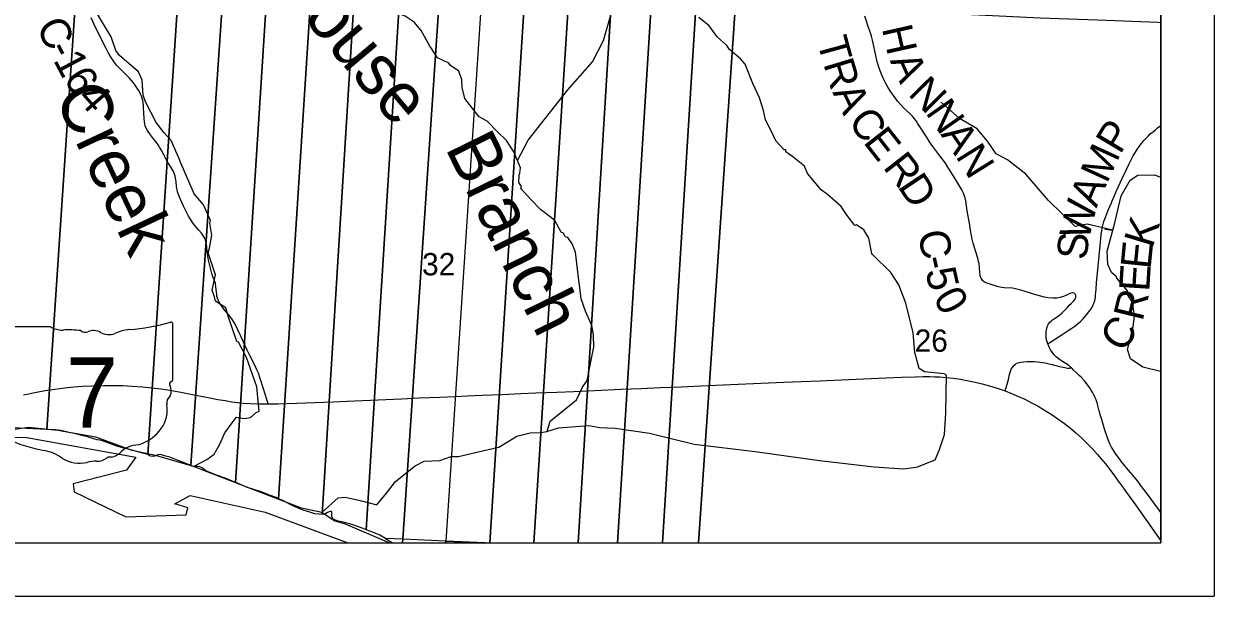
# Model space of a CAD drawing. Extents: x 0 to 34, y 0 to 22.
# Drawn here: x 6.766 to 9, y 14 to 15.074 of the extents above; entities that cross this region are included whole.
import ezdxf

# ---------------------------------------------------------------- set-up
doc = ezdxf.new("R2010")
doc.units = 0
for name, color, linetype in [('Default', 7, 'Continuous'), ('GM_X_County_Road', 7, 'Continuous'), ('GM_X_County_Road_Text', 7, 'Continuous'), ('GM_X_Major_River', 7, 'Continuous'), ('GM_X_Minor_River', 7, 'Continuous'), ('GM_X_Minor_River_Text', 7, 'Continuous'), ('GM_X_Section', 7, 'Continuous'), ('GM_X_Section_Text', 7, 'Continuous'), ('GM_X_State_Route', 7, 'Continuous'), ('GM_X_State_Shield', 7, 'Continuous'), ('SH_Cut_Line', 7, 'Continuous'), ('SH_Data', 7, 'Continuous')]:
    doc.layers.add(name, color=color, linetype=linetype)

msp = doc.modelspace()

# ---------------------------------------------------------------- linework, layer by layer
at = {"layer": 'Default'}
msp.add_lwpolyline([(6.746, 14.2985), (6.7712, 14.2974), (6.976, 14.2607), (6.9586, 14.2364), (6.8584, 14.2105), (6.8604, 14.196), (6.9571, 14.149), (7.0704, 14.1528), (7.0738, 14.1658), (7.0492, 14.1735), (7.0778, 14.1886), (7.2187, 14.1579), (7.3738, 14.1), (8.9, 14.1), (8.9, 19.1797)], dxfattribs=at)
for points in [[(7.6316, 14.1), (7.6406, 14.1), (7.7063, 15.1284), (7.6256, 15.132), (7.558, 14.1033)], [(7.6406, 14.1), (7.7231, 14.1), (7.7887, 15.1248), (7.7089, 15.1283), (7.7063, 15.1284)], [(7.7231, 14.1), (7.806, 14.1), (7.8688, 15.1212), (7.7887, 15.1248)], [(7.806, 14.1), (7.88, 14.1), (7.9439, 15.1179), (7.8688, 15.1212)], [(7.88, 14.1), (7.9647, 14.1), (8.0279, 15.1141), (7.9439, 15.1179)], [(7.9647, 14.1), (8.0319, 14.1), (8.1017, 15.1109), (8.0279, 15.1141)], [(8.0319, 14.1), (8.9, 14.1), (8.9, 15.0758), (8.8945, 15.0761), (8.7811, 15.0807), (8.6731, 15.0846), (8.5585, 15.09), (8.4462, 15.0952), (8.3272, 15.1001), (8.2115, 15.1046), (8.1017, 15.1109)], [(7.4602, 14.1), (7.4765, 14.1), (7.477, 14.1069), (7.4448, 14.1083), (7.453, 14.103), (7.4572, 14.1007)], [(7.4765, 14.1), (7.5578, 14.1), (7.558, 14.1033), (7.477, 14.1069)], [(7.5578, 14.1), (7.6316, 14.1), (7.558, 14.1033)]]:
    msp.add_lwpolyline(points, close=True, dxfattribs=at)
at = {"layer": 'GM_X_County_Road'}
for points in [[(7.2244, 14.3606), (7.2219, 14.3688), (7.2156, 14.3892), (7.2096, 14.4082), (7.206, 14.4183), (7.2034, 14.4246), (7.2015, 14.4291), (7.1959, 14.4397), (7.1898, 14.4516), (7.1852, 14.4614), (7.178, 14.4767), (7.173, 14.4881), (7.1675, 14.4999), (7.1622, 14.5106), (7.1573, 14.5185), (7.1524, 14.5252), (7.1418, 14.538), (7.1353, 14.5466), (7.1322, 14.5513), (7.1303, 14.5553), (7.129, 14.5592), (7.1282, 14.5625), (7.1277, 14.5666), (7.1273, 14.5709), (7.1262, 14.5801), (7.1252, 14.5863), (7.1229, 14.5932), (7.1204, 14.5994), (7.1185, 14.6053), (7.1152, 14.6178), (7.1124, 14.6304), (7.1111, 14.6381), (7.1099, 14.6469), (7.109, 14.6552), (7.1079, 14.6638), (7.107, 14.6679), (7.1051, 14.6721), (7.103, 14.6757), (7.099, 14.6811), (7.0942, 14.6868), (7.0898, 14.6919), (7.0867, 14.6955), (7.0823, 14.7011), (7.0784, 14.707), (7.0751, 14.7129), (7.0657, 14.7315), (7.0584, 14.7471), (7.0559, 14.7538), (7.0543, 14.7586), (7.0538, 14.7622), (7.0526, 14.7686), (7.0516, 14.7771), (7.0512, 14.781), (7.0506, 14.7848), (7.0499, 14.7877), (7.0485, 14.7918), (7.0458, 14.7978), (7.0385, 14.8096), (7.0352, 14.815), (7.0318, 14.8216), (7.0277, 14.8295), (7.0237, 14.8371), (7.0206, 14.8426), (7.0177, 14.8469), (7.0149, 14.851), (7.0092, 14.8583), (7.0033, 14.8654), (6.9976, 14.8735), (6.9955, 14.8779), (6.9937, 14.8823), (6.9929, 14.8862), (6.9923, 14.8895), (6.9914, 14.8967), (6.991, 14.9063), (6.9906, 14.9168), (6.9904, 14.9207), (6.9899, 14.9259), (6.9893, 14.9298), (6.9881, 14.9345), (6.9866, 14.9381), (6.9848, 14.9418), (6.9832, 14.9451), (6.9811, 14.949), (6.9785, 14.9532), (6.9745, 14.9589), (6.9709, 14.9638), (6.9678, 14.9676), (6.9638, 14.9719), (6.9609, 14.975), (6.9557, 14.9799), (6.9519, 14.9836), (6.9469, 14.9884), (6.9398, 14.9964), (6.9347, 15.003), (6.9297, 15.0108), (6.9268, 15.0156), (6.9243, 15.0199), (6.9197, 15.0287), (6.9161, 15.0355), (6.9122, 15.044), (6.9012, 15.0659), (6.8919, 15.0851)], [(8.6876, 14.4735), (8.6863, 14.4774), (8.6853, 14.4808), (8.6848, 14.4851), (8.6846, 14.4894), (8.6847, 14.4944), (8.6853, 14.5008), (8.6864, 14.5046), (8.6873, 14.5074), (8.6893, 14.511), (8.6916, 14.5139), (8.6937, 14.5162), (8.6968, 14.5187), (8.7022, 14.5224), (8.7069, 14.5254), (8.7104, 14.5279), (8.7146, 14.5314), (8.7202, 14.537), (8.7248, 14.5418), (8.7274, 14.5452), (8.7319, 14.5495), (8.7361, 14.5535), (8.7384, 14.5563), (8.7397, 14.5589), (8.7403, 14.5612), (8.7404, 14.5628), (8.7402, 14.5646), (8.7395, 14.5662), (8.7385, 14.5675), (8.7371, 14.5686), (8.7354, 14.5691), (8.7335, 14.5692), (8.7312, 14.5686), (8.7281, 14.5674), (8.723, 14.5648), (8.7169, 14.5624), (8.7103, 14.5602), (8.7044, 14.5594), (8.6979, 14.5588), (8.6879, 14.5599), (8.6818, 14.561), (8.6697, 14.5641), (8.6589, 14.567), (8.6434, 14.5721), (8.6348, 14.5749), (8.6273, 14.5768), (8.6213, 14.5776), (8.606, 14.5785), (8.6017, 14.5788), (8.5977, 14.5796), (8.5927, 14.5811), (8.5776, 14.5858), (8.572, 14.5878), (8.5689, 14.5892), (8.566, 14.5916), (8.5637, 14.5946), (8.5626, 14.5968), (8.5615, 14.5992), (8.5608, 14.6023), (8.5601, 14.6073), (8.5594, 14.6166), (8.5586, 14.6243), (8.5579, 14.6278), (8.5562, 14.6343), (8.552, 14.6477), (8.5477, 14.662), (8.5457, 14.6697), (8.5443, 14.6765), (8.5428, 14.6867), (8.5408, 14.7001), (8.5397, 14.7061), (8.5378, 14.7163), (8.5364, 14.7232), (8.5351, 14.7326), (8.5338, 14.7415), (8.5324, 14.7475), (8.5309, 14.7524), (8.5294, 14.7558), (8.5261, 14.7624), (8.5149, 14.781), (8.5055, 14.7963), (8.5003, 14.8048), (8.4956, 14.8122), (8.4894, 14.8206), (8.4834, 14.8285), (8.4719, 14.8439), (8.4659, 14.8525), (8.4612, 14.8596), (8.4469, 14.882), (8.4432, 14.8876), (8.4405, 14.8916), (8.4376, 14.8958), (8.4336, 14.9005), (8.4292, 14.9047), (8.4175, 14.9158), (8.4123, 14.9211), (8.4065, 14.9278), (8.4009, 14.935), (8.393, 14.9464), (8.3877, 14.9547), (8.3839, 14.9616), (8.3789, 14.9718), (8.3742, 14.9826), (8.3711, 14.9907), (8.3687, 14.9985), (8.3669, 15.0049), (8.3656, 15.011), (8.3632, 15.0228), (8.3613, 15.0316), (8.3588, 15.0431), (8.3567, 15.0506), (8.3553, 15.0548), (8.3519, 15.0653), (8.3441, 15.0884)], [(8.6876, 14.4735), (8.6885, 14.474), (8.6914, 14.4757), (8.7022, 14.4827), (8.7148, 14.4909), (8.7259, 14.4983), (8.733, 14.503), (8.7384, 14.5068), (8.7428, 14.51), (8.7456, 14.5124), (8.7496, 14.5161), (8.7528, 14.5192), (8.7568, 14.5234), (8.7605, 14.5278), (8.7649, 14.5333), (8.7694, 14.5392), (8.7722, 14.5446), (8.7743, 14.5495), (8.7755, 14.5531), (8.7764, 14.557), (8.7772, 14.5616), (8.7775, 14.5653), (8.7782, 14.5752), (8.779, 14.5882), (8.7808, 14.6059), (8.7821, 14.6193), (8.7833, 14.6317), (8.7847, 14.6455), (8.787, 14.6698), (8.788, 14.6789), (8.7888, 14.6853), (8.7895, 14.6893), (8.7904, 14.6932), (8.7931, 14.7027), (8.7964, 14.7125), (8.8011, 14.724), (8.807, 14.7379), (8.8087, 14.7419), (8.8115, 14.7487), (8.8162, 14.759), (8.8272, 14.7836), (8.8345, 14.799), (8.8398, 14.8101), (8.8479, 14.8262), (8.8521, 14.8333), (8.8574, 14.8414), (8.8615, 14.8468), (8.8643, 14.8501), (8.8682, 14.8549), (8.8729, 14.8601), (8.8762, 14.8633), (8.8801, 14.8671), (8.8858, 14.8718), (8.8896, 14.8749), (8.8939, 14.8784), (8.9, 14.8832)], [(8.732, 14.4284), (8.7303, 14.4299), (8.728, 14.4321), (8.7231, 14.4357), (8.7205, 14.4374), (8.7151, 14.4404), (8.7094, 14.4442), (8.7041, 14.4486), (8.6995, 14.4528), (8.6956, 14.4578), (8.6927, 14.4624), (8.6909, 14.4659), (8.6894, 14.4688), (8.6881, 14.472), (8.6876, 14.4735)], [(8.6074, 14.3851), (8.6113, 14.3976), (8.6137, 14.4066), (8.6159, 14.4156), (8.6172, 14.4204), (8.6182, 14.4233), (8.6192, 14.4259), (8.6208, 14.4287), (8.6225, 14.4312), (8.6241, 14.433), (8.6262, 14.4348), (8.6282, 14.4363), (8.6313, 14.4378), (8.6341, 14.4386), (8.6373, 14.4392), (8.6429, 14.4398), (8.6491, 14.4402), (8.6558, 14.4405), (8.6624, 14.4404), (8.6686, 14.4399), (8.6729, 14.4393), (8.6779, 14.4385), (8.683, 14.4375), (8.6877, 14.4365), (8.6959, 14.4344), (8.7098, 14.4311), (8.7194, 14.4288), (8.7248, 14.4279), (8.7287, 14.4278), (8.732, 14.4284)], [(8.9, 14.1572), (8.8974, 14.1607), (8.8868, 14.1749), (8.8767, 14.1886), (8.8681, 14.2002), (8.8624, 14.2079), (8.8564, 14.2156), (8.8496, 14.2236), (8.8287, 14.2492), (8.8223, 14.2576), (8.816, 14.266), (8.8133, 14.2698), (8.8096, 14.2755), (8.8074, 14.2795), (8.8041, 14.2861), (8.8011, 14.2933), (8.7983, 14.3009), (8.7947, 14.3116), (8.792, 14.3199), (8.7888, 14.3314), (8.7869, 14.3382), (8.7843, 14.3479), (8.7822, 14.3554), (8.7801, 14.3626), (8.7782, 14.3682), (8.7764, 14.3724), (8.7745, 14.3767), (8.7722, 14.3813), (8.7691, 14.3868), (8.7663, 14.391), (8.7624, 14.3966), (8.7569, 14.4035), (8.7502, 14.4109), (8.7467, 14.4143), (8.7435, 14.4173), (8.7412, 14.4194), (8.7356, 14.4247), (8.7341, 14.4263), (8.7333, 14.4271), (8.732, 14.4284)]]:
    msp.add_lwpolyline(points, dxfattribs=at)
at = {"layer": 'GM_X_Major_River'}
msp.add_lwpolyline([(7.4517, 14.1), (7.3694, 14.135), (7.3482, 14.1414), (7.3254, 14.1569), (7.2868, 14.1652), (7.1927, 14.2015), (7.0843, 14.2435), (7.0153, 14.2635), (6.969, 14.2733), (6.9012, 14.2986), (6.8397, 14.3092), (6.8303, 14.3107), (6.7738, 14.3167), (6.7492, 14.3128)], dxfattribs=at)
at = {"layer": 'GM_X_Minor_River'}
for points in [[(7.6922, 14.8173), (7.7125, 14.8558), (7.7868, 14.9502), (7.8334, 15.0027), (7.8539, 15.0426), (7.8692, 15.0968), (7.8662, 15.1356), (7.8471, 15.1674), (7.8077, 15.2028), (7.7982, 15.2263), (7.7898, 15.2607), (7.7756, 15.2893), (7.7455, 15.3305), (7.7326, 15.354), (7.7183, 15.4065)], [(7.5633, 15.0001), (7.5423, 15.0098), (7.5298, 15.0295), (7.5279, 15.0318), (7.5116, 15.0614), (7.4987, 15.0766), (7.4817, 15.0883), (7.4636, 15.0947), (7.439, 15.1095), (7.4333, 15.1099), (7.4318, 15.1159), (7.4216, 15.1205), (7.4095, 15.1349), (7.3898, 15.1459), (7.3845, 15.1508), (7.3739, 15.158), (7.3535, 15.199), (7.3213, 15.2502), (7.3201, 15.2582), (7.302, 15.3), (7.3016, 15.3106), (7.3, 15.3167), (7.2982, 15.3155)], [(7.0843, 14.2435), (7.109, 14.2563), (7.1233, 14.2662), (7.1331, 14.2841), (7.1433, 14.3066), (7.1603, 14.3302), (7.1652, 14.3359), (7.18, 14.3332), (7.1913, 14.3352), (7.2019, 14.3443), (7.2072, 14.3474), (7.2033, 14.3926), (7.1836, 14.448), (7.1689, 14.4765), (7.1658, 14.4776), (7.1511, 14.5198), (7.1499, 14.5236), (7.1446, 14.5407), (7.1253, 14.5532), (7.1234, 14.5615), (7.1193, 14.5744), (7.1257, 14.603), (7.112, 14.644), (7.1143, 14.6527), (7.1188, 14.6774), (7.115, 14.6998), (7.1161, 14.7048), (7.1029, 14.734), (7.0855, 14.7549), (7.0589, 14.8152), (7.0582, 14.8194), (7.0423, 14.8547), (7.029, 14.8695), (7.0139, 14.8885), (6.9942, 14.9272), (6.99, 14.9397), (6.9881, 14.9682), (6.9809, 14.9834), (6.9454, 15.0141), (6.9385, 15.0236), (6.9298, 15.0491), (6.917, 15.0699), (6.9014, 15.0965)], [(7.7475, 14.3087), (7.7693, 14.316), (7.7939, 14.3175), (7.8264, 14.3203), (7.8468, 14.3165), (7.8755, 14.3154), (7.9398, 14.3057), (8.0241, 14.2854), (8.1383, 14.2712), (8.2593, 14.2547), (8.3618, 14.2424), (8.4166, 14.2391), (8.4404, 14.2419), (8.4434, 14.2426), (8.4763, 14.256), (8.4846, 14.275), (8.494, 14.3035), (8.4966, 14.3442), (8.4977, 14.4145), (8.4931, 14.4172), (8.4565, 14.4209), (8.4463, 14.4273), (8.4383, 14.4573), (8.4352, 14.4942), (8.4212, 14.55), (8.4083, 14.5842), (8.3928, 14.6074), (8.3584, 14.6407), (8.3572, 14.6426), (8.3519, 14.6715), (8.3421, 14.687), (8.3288, 14.6965), (8.3258, 14.6957), (8.3111, 14.714), (8.2997, 14.731), (8.2743, 14.7534), (8.2626, 14.7625), (8.2369, 14.7932), (8.2312, 14.8069), (8.2093, 14.8243), (8.196, 14.8334), (8.196, 14.8372), (8.1926, 14.8372), (8.1775, 14.8543), (8.1722, 14.8649), (8.1703, 14.8695), (8.1578, 14.8934), (8.154, 14.9112), (8.1468, 14.9348), (8.1339, 14.9621), (8.1195, 14.9982), (8.1112, 15.0084), (8.09, 15.0255), (8.0851, 15.0334), (8.0673, 15.0494), (8.0522, 15.0698), (8.0325, 15.0854)], [(7.3254, 14.1569), (7.3555, 14.1843), (7.3691, 14.1858), (7.3997, 14.1791), (7.4281, 14.1715), (7.4466, 14.1932), (7.4636, 14.2149), (7.5002, 14.2447), (7.5172, 14.2531), (7.5467, 14.2547), (7.5679, 14.2623), (7.5815, 14.2623), (7.6374, 14.275), (7.6575, 14.2796), (7.6858, 14.2972), (7.6911, 14.3002), (7.7164, 14.3063), (7.7357, 14.3071), (7.7478, 14.3087), (7.7534, 14.3281), (7.7606, 14.3338), (7.8029, 14.3685), (7.8146, 14.3921), (7.8233, 14.4046), (7.8301, 14.4396), (7.8357, 14.4674), (7.8353, 14.4902), (7.8319, 14.5076), (7.8198, 14.535), (7.8118, 14.5578), (7.808, 14.5889), (7.8076, 14.5923), (7.8015, 14.6455), (7.7951, 14.6611), (7.7868, 14.6729), (7.7819, 14.674), (7.7788, 14.6808), (7.7743, 14.6831), (7.7622, 14.7047), (7.7535, 14.7119), (7.7353, 14.7256), (7.7175, 14.7445), (7.6986, 14.765), (7.6997, 14.7684), (7.6948, 14.776), (7.6956, 14.7905), (7.6967, 14.7939), (7.6978, 14.8034), (7.6853, 14.8338), (7.6717, 14.855), (7.6547, 14.8713), (7.6354, 14.891), (7.6202, 14.8994), (7.6127, 14.9089), (7.5934, 14.9335), (7.5888, 14.9544), (7.588, 14.9685), (7.582, 14.9848), (7.5668, 14.9958), (7.5632, 15.0002)], [(8.7949, 14.6887), (8.8097, 14.6865), (8.7616, 14.6977), (8.7388, 14.6935), (8.6889, 14.7425), (8.6465, 14.7917), (8.6118, 14.8183), (8.5909, 14.8296), (8.5747, 14.8536), (8.555, 14.8767), (8.5219, 14.8963), (8.4877, 14.9271)], [(8.9, 14.4213), (8.8995, 14.4215), (8.8659, 14.4298), (8.8432, 14.445), (8.8375, 14.4628), (8.848, 14.5046), (8.8503, 14.5263), (8.8469, 14.5518), (8.8381, 14.565), (8.837, 14.573), (8.8173, 14.5969), (8.8166, 14.5992), (8.8075, 14.6075), (8.8003, 14.6223), (8.7991, 14.647), (8.8135, 14.7007), (8.8251, 14.7509), (8.8425, 14.7802), (8.8569, 14.7901), (8.8871, 14.7905), (8.9, 14.7863)]]:
    msp.add_lwpolyline(points, dxfattribs=at)
at = {"layer": 'GM_X_Section'}
for points in [[(6.6679, 15.168), (6.8659, 15.1648), (6.8091, 14.313), (6.7968, 14.3133), (6.7574, 14.3154), (6.7525, 14.3161), (6.7499, 14.3155), (6.742, 14.3162), (6.7242, 14.3154), (6.7094, 14.3154), (6.7014, 14.3158), (6.6848, 14.315), (6.6749, 14.3142), (6.656, 14.3134), (6.6393, 14.313), (6.6211, 14.3149), (6.6082, 14.3162)], [(6.8659, 15.1648), (7.0576, 15.1572), (6.9982, 14.2655), (6.9883, 14.2685), (6.9712, 14.273), (6.9538, 14.2778), (6.9424, 14.2808), (6.9219, 14.2883), (6.9136, 14.2913), (6.9083, 14.2928), (6.9034, 14.2932), (6.8992, 14.2947), (6.8855, 14.2988), (6.8722, 14.3022), (6.8635, 14.3044), (6.851, 14.307), (6.8351, 14.3107), (6.8249, 14.3118), (6.8091, 14.313)], [(7.1412, 15.1536), (7.0789, 14.2451), (7.0683, 14.2494), (7.0524, 14.2558), (7.0459, 14.2584), (7.0399, 14.2607), (7.03, 14.2633), (7.022, 14.2656), (7.0175, 14.2652), (7.0126, 14.2633), (7.0088, 14.2621), (7.0042, 14.2625), (7.0016, 14.2632), (6.9982, 14.2655), (7.0576, 15.1572)], [(7.2228, 15.15), (7.1628, 14.2135), (7.1438, 14.2213), (7.1275, 14.2273), (7.1104, 14.2337), (7.1051, 14.237), (7.1006, 14.2408), (7.0964, 14.2427), (7.0918, 14.2431), (7.0854, 14.2434), (7.0812, 14.2442), (7.0789, 14.2451), (7.1412, 15.1536)], [(7.3055, 15.1463), (7.2438, 14.1829), (7.2394, 14.1849), (7.2288, 14.189), (7.2102, 14.1961), (7.2011, 14.1991), (7.184, 14.2047), (7.1666, 14.2119), (7.1628, 14.2135), (7.2228, 15.15)], [(7.3872, 15.1426), (7.3259, 14.1534), (7.3203, 14.1537), (7.3119, 14.1548), (7.3024, 14.1574), (7.2903, 14.1615), (7.2751, 14.1675), (7.2679, 14.1709), (7.252, 14.1792), (7.2438, 14.1829), (7.3055, 15.1463)], [(7.472, 15.1389), (7.4083, 14.1246), (7.4029, 14.1267), (7.3851, 14.1331), (7.3771, 14.1357), (7.3692, 14.1376), (7.3635, 14.1394), (7.3559, 14.1406), (7.351, 14.1424), (7.3468, 14.1447), (7.3449, 14.1466), (7.3441, 14.1492), (7.3441, 14.156), (7.3437, 14.1579), (7.343, 14.1587), (7.3418, 14.1591), (7.3407, 14.1591), (7.3358, 14.1568), (7.3305, 14.1541), (7.3259, 14.1534), (7.3872, 15.1426)], [(7.5463, 15.1356), (7.477, 14.1069), (7.4448, 14.1083), (7.4337, 14.1143), (7.4219, 14.1192), (7.4083, 14.1246), (7.472, 15.1389)], [(7.6256, 15.132), (7.558, 14.1033), (7.477, 14.1069), (7.5463, 15.1356)]]:
    msp.add_lwpolyline(points, close=True, dxfattribs=at)
at = {"layer": 'GM_X_State_Route'}
msp.add_lwpolyline([(6.7652, 14.3776), (6.7896, 14.3827), (6.806, 14.3857), (6.8239, 14.3884), (6.843, 14.3909), (6.8594, 14.3926), (6.8759, 14.3939), (6.8933, 14.3948), (6.9157, 14.3953), (6.9325, 14.3954), (6.9517, 14.395), (6.9691, 14.3941), (6.9886, 14.3927), (7.0058, 14.391), (7.0227, 14.389), (7.0401, 14.3862), (7.0574, 14.3831), (7.0889, 14.3769), (7.115, 14.3718), (7.1299, 14.3691), (7.1437, 14.3668), (7.1559, 14.3649), (7.167, 14.3634), (7.1775, 14.3623), (7.191, 14.3614), (7.2065, 14.3608), (7.2244, 14.3606), (7.2425, 14.3609), (7.2779, 14.3621), (7.3456, 14.3649), (7.3872, 14.3667), (7.4747, 14.3705), (7.5076, 14.372), (7.5467, 14.3736), (7.5746, 14.3747), (7.5988, 14.3757), (7.6262, 14.3769), (7.6635, 14.3785), (7.6989, 14.3801), (7.7266, 14.3812), (7.7659, 14.3828), (7.7982, 14.3843), (7.8376, 14.386), (7.8868, 14.3881), (7.9245, 14.3898), (7.9606, 14.3914), (7.9997, 14.393), (8.0363, 14.3946), (8.1064, 14.3977), (8.1921, 14.4014), (8.2247, 14.4027), (8.2604, 14.4042), (8.3138, 14.4066), (8.3845, 14.4096), (8.4131, 14.4109), (8.4387, 14.4117), (8.4535, 14.412), (8.4663, 14.412), (8.4754, 14.4118), (8.4844, 14.4113), (8.4973, 14.4103), (8.5101, 14.4089), (8.5238, 14.407), (8.5359, 14.4048), (8.5511, 14.4017), (8.5645, 14.3985), (8.5783, 14.3947), (8.5925, 14.3903), (8.6074, 14.3851), (8.6195, 14.3805), (8.6327, 14.3749), (8.6445, 14.3694), (8.6573, 14.363), (8.6693, 14.3564), (8.6817, 14.3492), (8.6943, 14.3412), (8.7067, 14.3328), (8.7193, 14.3237), (8.7301, 14.3152), (8.7406, 14.3064), (8.7512, 14.2968), (8.7606, 14.2877), (8.7709, 14.2769), (8.781, 14.2659), (8.7875, 14.2583), (8.7958, 14.2482), (8.8053, 14.2359), (8.8134, 14.2249), (8.82, 14.2158), (8.8266, 14.2068), (8.8355, 14.1948), (8.8521, 14.1715), (8.879, 14.1335), (8.9, 14.104)], dxfattribs=at)
at = {"layer": 'GM_X_State_Shield'}
for p, q in [((6.8156, 14.5056), (6.7191, 14.5056)), ((7.0454, 14.4058), (7.0454, 14.5105)), ((7.0454, 14.4059), (7.0454, 14.4058))]:
    msp.add_line(p, q, dxfattribs=at)
for centre, major_axis, start_param, end_param in [((6.8386, 14.5288), (0.037, 0), 4.042523, 4.731795), ((6.928, 14.7784), (0.3495, 0), 4.814394, 5.042369), ((7.0418, 14.511), (0.00367, 0), 6.141152, 7.989035), ((6.8509, 14.3932), (0.133, 0), 1.404758, 1.657858), ((6.8811, 14.5036), (0.0107, 0), 3.836095, 5.185415), ((6.8968, 14.4805), (0.0222, 0), 0.950623, 2.079405), ((6.9254, 14.5122), (0.0267, 0), 4.081561, 5.145723), ((6.9726, 14.4444), (0.0703, 0), 1.699011, 2.107814), ((7.0446, 14.3982), (0.00568, 0), 1.883978, 3.671073), ((7.0085, 14.3849), (0.0341, 0), 5.934695, 6.695948), ((7.0415, 14.4054), (0.00393, 0), 5.05454, 6.418171), ((7.0586, 14.362), (0.0248, 0), 2.387724, 3.262537), ((6.9476, 14.3487), (0.0874, 0), 5.101752, 6.440018), ((6.8601, 14.4703), (0.2524, 0), 4.195997, 4.488961), ((6.9845, 14.2458), (0.0479, 0), 1.647645, 2.488434), ((6.7848, 14.2121), (0.079, 0), 0.823519, 1.323587), ((6.8703, 14.2895), (0.0501, 0), 4.026481, 4.996735), ((6.9029, 14.2745), (0.0267, 0), 4.691044, 5.507374), ((6.927, 14.2551), (0.00752, 0), 1.147584, 2.315152), ((6.9238, 14.2826), (0.0282, 0), 4.937069, 5.64225), ((6.8992, 14.2203), (0.0412, 0), 1.495662, 1.94098)]:
    msp.add_ellipse(centre, major_axis=major_axis, ratio=0.8, start_param=start_param, end_param=end_param, dxfattribs=at)
at = {"layer": 'SH_Cut_Line'}
msp.add_lwpolyline([(6.746, 14.2985), (6.7712, 14.2974), (6.976, 14.2607), (6.9586, 14.2364), (6.8584, 14.2105), (6.8604, 14.196), (6.9571, 14.149), (7.0704, 14.1528), (7.0738, 14.1658), (7.0492, 14.1735), (7.0778, 14.1886), (7.2187, 14.1579), (7.3738, 14.1), (8.9, 14.1), (8.9, 20.9)], dxfattribs=at)
at = {"layer": 'SH_Data'}
for p, q in [((9, 21), (9, 14)), ((8.9, 20.9), (8.9, 14.1)), ((2.1, 14.1), (8.9, 14.1)), ((2, 14), (9, 14))]:
    msp.add_line(p, q, dxfattribs=at)

# ---------------------------------------------------------------- texts
at = {"layer": 'GM_X_County_Road_Text'}
for s, rotation, p in [('C', 297.5557, (6.7876, 15.0682)), ('H', 282.5735, (8.376, 15.0654)), ('T', 285.3497, (8.2543, 15.0416)), ('1', 297.852, (6.8202, 15.0058)), ('-', 297.6185, (6.8093, 15.0267)), ('R', 286.9005, (8.266, 14.999)), ('A', 294.0227, (8.3908, 15.0049)), ('6', 302.5796, (6.8391, 14.9705)), ('N', 314.5183, (8.4236, 14.941)), ('4', 311.2111, (6.8636, 14.9335)), ('A', 295.826, (8.2831, 14.9453)), ('N', 304.9086, (8.457, 14.9072)), ('C', 306.8329, (8.3111, 14.8902)), ('E', 308.0682, (8.3399, 14.8517)), ('A', 304.4074, (8.4856, 14.8663)), ('P', 58.982, (8.8235, 14.8273)), ('N', 301.8621, (8.5135, 14.8256)), ('M', 65.3393, (8.7986, 14.7727)), ('R', 307.9948, (8.3769, 14.8045)), ('D', 303.5294, (8.4049, 14.7687)), ('A', 66.6574, (8.7789, 14.7271)), ('W', 76.3164, (8.7641, 14.6655)), ('K', 73.1624, (8.8842, 14.6518)), ('C', 279.615, (8.4441, 14.6827)), ('S', 83.9975, (8.7605, 14.6294)), ('E', 84.3037, (8.8805, 14.6124)), ('-', 282.552, (8.4525, 14.6335)), ('5', 282.8033, (8.4576, 14.6105)), ('E', 86.4866, (8.878, 14.5705)), ('0', 298.7505, (8.4715, 14.5603)), ('R', 76.1921, (8.8652, 14.5142)), ('C', 53.8639, (8.8275, 14.4547))]:
    msp.add_text(s, height=0.0568, rotation=rotation, dxfattribs=at).set_placement(p)
at = {"layer": 'GM_X_Minor_River_Text'}
for s, rotation, p in [('Stillhouse', 310.1347, (7.1113, 15.2962)), ('Creek', 295.1343, (6.8221, 14.9382)), ('Branch', 296.1346, (7.5557, 14.8415))]:
    msp.add_text(s, height=0.09469, rotation=rotation, dxfattribs=at).set_placement(p)
at = {"layer": 'GM_X_Section_Text'}
for s, p in [('32', (7.5133, 14.6019)), ('26', (8.4378, 14.4585))]:
    msp.add_text(s, height=0.04186, rotation=0, dxfattribs=at).set_placement(p)
at = {"layer": 'GM_X_State_Shield'}
msp.add_text('7', height=0.1318, dxfattribs=at).set_placement((6.8445, 14.3161))

doc.saveas('drawing.dxf')
